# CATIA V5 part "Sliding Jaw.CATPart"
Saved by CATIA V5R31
Part number: Sliding Jaw
Bounding box of the stored display mesh (mm): x -32 to 32, y -16 to 16, z -9 to 36
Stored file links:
  D:\PROJECTS\Project 2021\US EDITION\CATIA V5 6R 2021\Resources\Part Files\c12_catia_v5_6r2021_prt\c12_catia_v5-6r2021 figr_12-19\Sliding Jaw.CATPart
  C:\Program Files\Dassault Systemes\B09\intel_a\reffiles\standard\MetricThickPitch.txt
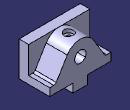
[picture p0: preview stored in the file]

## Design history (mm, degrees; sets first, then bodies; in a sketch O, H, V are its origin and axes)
Body1 (main body)
  Sketch1 on xy-plane, origin (0, 0, 0), H (1, 0, 0), V (0, 1, 0)
    line L1 (-32, -16) -> (32, -16)
    line L2 (32, -16) -> (32, 16)
    line L3 (32, 16) -> (-32, 16)
    line L4 (-32, 16) -> (-32, -16)
    distance H L1 = 16
    distance V L4 = 32
    length L4 = 32
    length L1 = 64
    horizontal: L1 H, L3 H
    vertical: L2 V, L4 V
  Pad1: profile Sketch1, direction (0, 0, 1), length 8
  Sketch2 on face of Pad1, origin (0, -16, 0), H (1, 0, 0), V (0, 0, 1)
    point P1 (-32, 0)
    line L1 (-32, 0) -> (32, 0)
    line L2 (32, 0) -> (32, 36)
    line L3 (32, 36) -> (-32, 36)
    line L4 (-32, 36) -> (-32, 0)
    reference projected line E1 (32, 0) -> (32, 8) from edge of Pad1
    reference projected line E2 (-32, 8) -> (-32, 0) from edge of Pad1
    length L2 = 36
    coincidence: P1 H, L2 E1, L4 E2
    horizontal: L1 H, L3 H
    vertical: L2 V, L4 V
  Pad2: profile Sketch2, direction (0, 1, 0), length 10
  Sketch3 on face of Pad1, origin (0, 16, 0), H (-1, 0, 0), V (0, 0, 1)
    arc A1 centre (0, 20) radius 16 from (13.6777, 28.3018) to (-13.6777, 28.3018) ccw
    point P1 (0, 20)
    reference projected line E1 (-32, 36) -> (32, 36) from edge of Pad2
    line L1 (-26, 8) -> (-13.6777, 28.3018)
    point P2 (-26, 8)
    line L2 (13.6777, 28.3018) -> (26, 8)
    point P3 (26, 8)
    reference projected line E2 (32, 8) -> (-32, 8) from edge of Pad1
    reference projected line E3 (32, 8) -> (-32, 8) from edge of Pad1
    line L3 (-26, 8) -> (26, 8)
    radius A1 = 16
    length L3 = 52
    distance V P3 = 26
    coincidence: P1 V, E2 P2, E3 P3
    tangency: A1 E1, L2 A1, L1 A1
    horizontal: L3 H
  Pad3: profile Sketch3, direction (0, -1, 0), up to the existing solid (limit type 2)
  Fillet1: radius 3, on 2 edges
  Sketch4 on face of Pad1, origin (-2.6964, 16, 22.8197), H (1, 0, 0), V (0, 0, -1)
    point P1 (2.6964, 2.8197)
    reference projected arc E1 centre (2.6964, 2.8197) radius 16 from (-10.9814, -5.4821) to (16.3741, -5.4821) ccw from edge of Pad3
    concentricity: P1 E1
  Hole1: placed by Sketch4, at (0, 16, 20) direction (0, -1, 0), diameter 12, depth 22, V-bottom angle 120
  Sketch5 on face of Pad1, origin (0, 16, 0), H (-1, 0, 0), V (0, 0, 1)
    point P1 (-7.75, 0)
    line L1 (-7.75, 0) -> (7.75, 0)
    line L2 (7.75, 0) -> (7.75, -9)
    line L3 (7.75, -9) -> (-7.75, -9)
    line L4 (-7.75, -9) -> (-7.75, 0)
    distance V L2 = 7.75
    length L3 = 15.5
    length L4 = 9
    coincidence: P1 H
    horizontal: L1 H, L3 H
    vertical: L2 V, L4 V
  Pad4: profile Sketch5, direction (0, -1, 0), length 32
  Sketch6 on face of Pad4, origin (-0.598, -1.2346, -9), H (1, 0, 0), V (0, -1, 0)
    point P1 (0.598, -9.2346)
    reference projected line E1 (8.348, -17.2346) -> (-7.152, -17.2346) from edge of Pad4
    reference projected line E2 (8.348, 14.7654) -> (8.348, -17.2346) from edge of Pad4
    distance P1 E1 = 8
    distance P1 E2 = 7.75
  Hole2: placed by Sketch6, at (0, 8, -9) direction (0, 0, 1), diameter 5, depth 16, V-bottom angle 120, threaded, thread diameter 6, thread depth 16, pitch 1
  RectPattern1: of Hole2, direction 1 instances 2, spacing 16, along edge of Pad4 reversed
  Sketch7 on face of Pad2, origin (-19.6018, -13.7351, 36), H (1, 0, 0), V (0, 1, 0)
    point P1 (19.6018, 17.7351)
    reference intersected line E1 through (19.6018, 0) direction (0, 1) from yz-plane
    reference projected line E2 (51.6018, -2.2649) -> (-12.3982, -2.2649) from edge of Pad2
    distance P1 E2 = 20
    coincidence: E1 P1
  Hole3: placed by Sketch7, at (0, 4, 36) direction (0, 0, -1), diameter 5, depth 16, V-bottom angle 120, counterbore diameter 10, counterbore depth 4, threaded, thread diameter 6, thread depth 11, pitch 1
